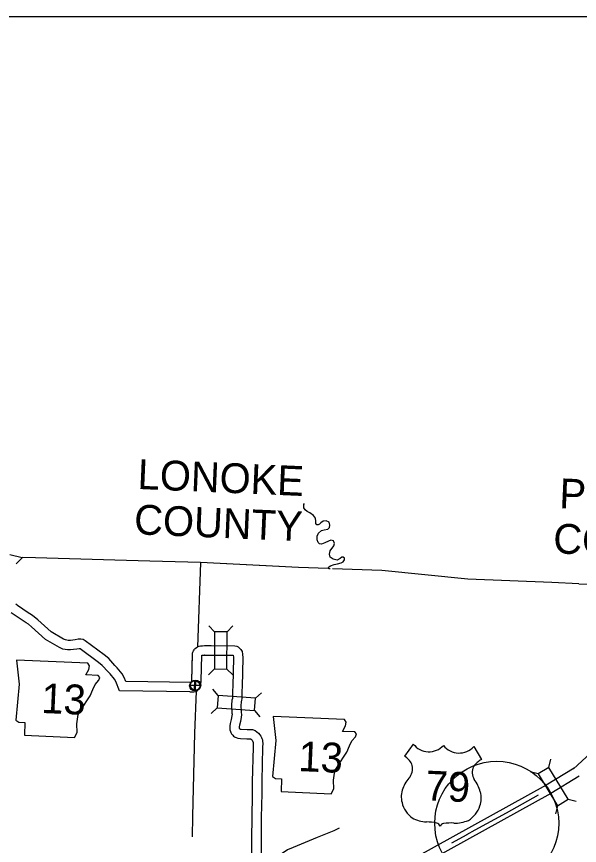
# Model space of a CAD drawing. Extents: x 1196286 to 1268366, y 2040822 to 2082115.
# Drawn here: x 1200093 to 1203681, y 2076830 to 2082115 of the extents above; entities that cross this region are included whole.
import ezdxf

# ---------------------------------------------------------------- set-up
doc = ezdxf.new("R2010")
doc.units = 0
for name, color, linetype in [('10', 7, 'Continuous'), ('55', 7, 'Continuous'), ('Default', 7, 'Continuous'), ('Level 100', 7, 'Continuous'), ('Level 78', 7, 'Continuous'), ('Level 8', 7, 'Continuous'), ('Level 84', 7, 'Continuous'), ('Level 87', 7, 'Continuous'), ('Level 95', 7, 'Continuous'), ('Level 96', 7, 'Continuous'), ('Level 98', 7, 'Continuous')]:
    doc.layers.add(name, color=color, linetype=linetype)

msp = doc.modelspace()

# ---------------------------------------------------------------- linework, layer by layer
at = {"layer": '10'}
msp.add_lwpolyline([(1202150.4, 2076940.5), (1202116.4, 2076923.6), (1202008.7, 2076880), (1201857.3, 2076817.3), (1201821, 2076800.8), (1201785.3, 2076778.5), (1201558.1, 2076623.9), (1201479.7, 2076569.9), (1201437.3, 2076546.6), (1201393.2, 2076527.1), (1201236, 2076471.6), (1201170.7, 2076445.2), (1201116.4, 2076419.2), (1201080.8, 2076396.6)], dxfattribs=at)
at = {"layer": '55'}
for points in [[(1203677.3, 2078498.2), (1204029.1, 2078492.6), (1204569.7, 2078521.8), (1204573.6, 2079234.1)], [(1202079.8, 2078594.6), (1202084.8, 2078605.7), (1202094.2, 2078612.5), (1202118.8, 2078621.3), (1202139.9, 2078625.9), (1202163.4, 2078631.3), (1202175.8, 2078638.7), (1202183, 2078651.2), (1202183.8, 2078662.4), (1202175.8, 2078667.5), (1202167.2, 2078667.2), (1202155.8, 2078660.4), (1202135.9, 2078649.3), (1202110.4, 2078654.2), (1202092.3, 2078668.5), (1202088, 2078687.5), (1202092.3, 2078707.8), (1202114.7, 2078739.6), (1202120.8, 2078754.2), (1202114.5, 2078771.3), (1202095.7, 2078776.6), (1202080.9, 2078770.7), (1202057.8, 2078759.5), (1202037, 2078751.4), (1202023.7, 2078751.9), (1202015.6, 2078760.6), (1202009, 2078778.5), (1202009.1, 2078801.9), (1202016.9, 2078820.5), (1202036.2, 2078837.8), (1202053.1, 2078842), (1202078, 2078847.3), (1202089, 2078857.6), (1202090.7, 2078872.3), (1202085.9, 2078890.5), (1202066.1, 2078898.7), (1202047.9, 2078896.9), (1202033.4, 2078887.2), (1202023.7, 2078878.3), (1202016.8, 2078874), (1202006.8, 2078874.9), (1202000.9, 2078883.5), (1202001.2, 2078896.6), (1201997.9, 2078916.3), (1201986.5, 2078933.1), (1201962.6, 2078950.4), (1201945.4, 2078959.7), (1201933.8, 2078970.1), (1201925.3, 2078983.2), (1201925.4, 2079002.9), (1201929.4, 2079009.1)], [(1200942, 2078643), (1200719.1, 2078648), (1200214.6, 2078663.6), (1200128.6, 2078666.3)], [(1201767.2, 2078607.4), (1201264.8, 2078633.9), (1200942, 2078643)], [(1202079.8, 2078594.6), (1201890, 2078601), (1201264.8, 2078633.9), (1200942, 2078643)], [(1201264.8, 2078633.9), (1201245.8, 2078094.7)], [(1201264.8, 2078633.9), (1201245.8, 2078094.7)], [(1202091.8, 2078594.2), (1202083.2, 2078594.5)], [(1203677.3, 2078498.2), (1203505.7, 2078505.7), (1202970.4, 2078527.8), (1202420.7, 2078583.1), (1202106.3, 2078593.7)], [(1201237.5, 2077813.2), (1201227.7, 2077546.2), (1201215.6, 2077015.9), (1201211.8, 2076884)], [(1201237.5, 2077812.6), (1201227.7, 2077546.2), (1201215.6, 2077015.9), (1201211.8, 2076884)]]:
    msp.add_lwpolyline(points, dxfattribs=at)
at = {"layer": 'Default'}
for p, q in [((1202621.9, 2077476.4), (1202566.6, 2077398.4)), ((1203007.6, 2077459.9), (1203056.1, 2077377.5))]:
    msp.add_line(p, q, dxfattribs=at)
msp.add_lwpolyline([(1201728.7, 2077652.5), (1201745, 2077499.4), (1201725, 2077269.1), (1201744.7, 2077255.6), (1201782.8, 2077253.9), (1201779.3, 2077172.8), (1202098.7, 2077159.1), (1202115.4, 2077191.4), (1202112.6, 2077244.9), (1202122.8, 2077305.4), (1202152.7, 2077352.4), (1202172, 2077387.1), (1202199, 2077424.1), (1202215.9, 2077464), (1202230, 2077496.4), (1202254, 2077523.3), (1202259.9, 2077540.9), (1202250.3, 2077554), (1202171.7, 2077557.3), (1202190.9, 2077592.1), (1202194.4, 2077614.8), (1202184.7, 2077632.8)], close=True, dxfattribs=at)
for centre, radius, start, end in [((1202722, 2077553.6), 126.4, 217.623, 317.2181), ((1202914.5, 2077545.3), 126.4, 217.8778, 317.4729), ((1202493.8, 2077284.9), 134.9, 28.3289, 57.5362), ((1203118.9, 2077258.1), 134.9, 117.5597, 146.767), ((1202525, 2077319.1), 92.5, 326.3584, 18.7587), ((1203090.7, 2077294.9), 92.5, 156.3372, 208.7375), ((1202758.5, 2077119.4), 215.7, 136.5044, 160.2393), ((1202841, 2077115.9), 215.7, 14.8566, 38.5915), ((1202688.1, 2077140.1), 142.6, 158.5056, 194.9298), ((1202912.9, 2077130.5), 142.6, 340.1661, 16.5903), ((1202711.3, 2077139.5), 165, 192.6554, 234.6791), ((1202889.7, 2077131.9), 165, 300.4168, 342.4405), ((1202716.6, 2077191.3), 211.8, 241.625, 267.1258), ((1202695.8, 2076591.9), 388, 78.7421, 88.5018), ((1202759.2, 2076937.4), 37.2, 25.5822, 70.5343), ((1202824.8, 2076934.6), 37.2, 104.5616, 149.5137), ((1202858.3, 2076584.9), 388, 86.5941, 96.3538), ((1202888.9, 2077183.9), 211.8, 267.9701, 293.4709)]:
    msp.add_arc(centre, radius, start, end, dxfattribs=at)
at = {"layer": 'Level 100'}
for p, q in [((1201261.7, 2077846.4), (1201196.7, 2077848.6)), ((1201202, 2077852.2), (1201267.1, 2077851)), ((1201228.1, 2077815), (1201230.3, 2077880)), ((1201233.9, 2077819.1), (1201235.2, 2077884.2))]:
    msp.add_line(p, q, dxfattribs=at)
for centre, radius in [((1201229.2, 2077847.5), 32.5), ((1201234.6, 2077851.6), 32.6)]:
    msp.add_circle(centre, radius, dxfattribs=at)
at = {"layer": 'Level 78'}
msp.add_lwpolyline([(1200092.7, 2078011.8), (1200109, 2077858.7), (1200088.9, 2077628.4), (1200108.7, 2077614.8), (1200146.7, 2077613.2), (1200143.2, 2077532.1), (1200462.7, 2077518.4), (1200479.3, 2077550.7), (1200476.5, 2077604.2), (1200486.7, 2077664.7), (1200516.7, 2077711.7), (1200536, 2077746.4), (1200562.9, 2077783.4), (1200579.9, 2077823.3), (1200594, 2077855.7), (1200618, 2077882.6), (1200623.8, 2077900.1), (1200614.2, 2077913.2), (1200535.6, 2077916.6), (1200554.9, 2077951.3), (1200558.4, 2077974), (1200548.6, 2077992)], close=True, dxfattribs=at)
at = {"layer": 'Level 8'}
msp.add_lwpolyline([(1196285.8, 2082114.9), (1207540.7, 2082114.9), (1207563, 2069523.3), (1196285.8, 2069523.3)], close=True, dxfattribs=at)
for points in [[(1202964.4, 2076899.4), (1203017.1, 2076928.9), (1203215.4, 2077038.3), (1203420.2, 2077152.8)], [(1202866.8, 2076846.1), (1202964.6, 2076899.5)]]:
    msp.add_lwpolyline(points, dxfattribs=at)
msp.add_circle((1203153.8, 2076971.3), 395.3, dxfattribs=at)
at = {"layer": 'Level 84'}
for points in [[(1204746.9, 2078438), (1204744.6, 2078433.5), (1204739.6, 2078415.9), (1204735.2, 2078403.8), (1204733, 2078396), (1204729.7, 2078385.5), (1204726.2, 2078372.7), (1204722.8, 2078362.5), (1204719, 2078350.6), (1204715.6, 2078337.7), (1204710.9, 2078325.5), (1204704.4, 2078309.6), (1204695.5, 2078294.9), (1204693.5, 2078290.6), (1204689.3, 2078285.4), (1204685.7, 2078280), (1204682.6, 2078276.6), (1204672.4, 2078266.1), (1204665.8, 2078258.9), (1203642.8, 2077318.1)], [(1203647.6, 2077321.7), (1203469.2, 2077213.2), (1202397.6, 2076620.1), (1202358.9, 2076604.5), (1202331.8, 2076591.8), (1202297.8, 2076576.5), (1202278, 2076569.9), (1202246.6, 2076561.7), (1202206.6, 2076555.5), (1201875.5, 2076511.7), (1201613.8, 2076477.3), (1201433.8, 2076454.5), (1201422.2, 2076453.1), (1201405.9, 2076452.7), (1201391.5, 2076453), (1201353.5, 2076452.1), (1201200.1, 2076454.6)], [(1203678.7, 2077270.4), (1203499.3, 2077161.3), (1202423.5, 2076565.9), (1202382.9, 2076549.5), (1202356.9, 2076537.2), (1202319.6, 2076520.6), (1202295.1, 2076512.4), (1202258.8, 2076502.9), (1202215.1, 2076496.1), (1201883.3, 2076452.2), (1201621.5, 2076417.8), (1201441.1, 2076395), (1201426.6, 2076393.2), (1201406.2, 2076392.6), (1201391.5, 2076393), (1201353.7, 2076392.1), (1201197.9, 2076394.6), (1201197.6, 2076394.6)]]:
    msp.add_lwpolyline(points, dxfattribs=at)
at = {"layer": 'Level 87'}
for p, q in [((1201278.5, 2078103.4), (1201292, 2078103.8)), ((1201214.2, 2078047.5), (1201214.5, 2078050.6)), ((1201293.5, 2078043.8), (1201291.8, 2078043.8)), ((1201209.8, 2077882.5), (1201209.6, 2077879.9)), ((1201269.4, 2077875.7), (1201269.6, 2077878.3)), ((1201212.8, 2077808.5), (1201216.5, 2077808.6))]:
    msp.add_line(p, q, dxfattribs=at)
for points in [[(1201209.6, 2077879.9), (1201214.4, 2078053.3)], [(1201214.4, 2078053.3), (1201217.1, 2078062.3), (1201220.1, 2078069.6), (1201224.6, 2078076.3), (1201228.1, 2078080.4), (1201232.6, 2078085.3), (1201239.7, 2078091), (1201247.6, 2078095.8), (1201256.6, 2078099.4), (1201265.1, 2078101.8), (1201273.5, 2078102.8), (1201291.1, 2078103.8)], [(1201214.5, 2078050.6), (1201215.2, 2078055.9), (1201217.1, 2078062.3), (1201220.1, 2078069.6), (1201224.6, 2078076.3), (1201228.1, 2078080.4), (1201232.6, 2078085.3), (1201239.7, 2078091), (1201247.6, 2078095.8), (1201256.6, 2078099.4), (1201265.1, 2078101.8), (1201278.5, 2078103.4)], [(1201291.1, 2078103.8), (1201485.6, 2078103.2)], [(1201292, 2078103.8), (1201334.1, 2078103.6)], [(1201485.6, 2078103.2), (1201497.1, 2078099.4), (1201504.8, 2078095.2), (1201514.6, 2078088.2), (1201523.2, 2078079.2), (1201531.4, 2078066.1), (1201534.3, 2078049.1), (1201536.3, 2078025.4)], [(1201209.6, 2077879.9), (1201214.2, 2078047.5)], [(1201269.6, 2077878.3), (1201274.1, 2078042.8)], [(1201269.6, 2077878.3), (1201274.1, 2078042.8)], [(1201274.1, 2078042.8), (1201292.7, 2078043.8)], [(1201274.1, 2078042.8), (1201293.5, 2078043.8)], [(1201291.8, 2078043.8), (1201474.6, 2078043.2)], [(1201292.7, 2078043.8), (1201333.9, 2078043.6)], [(1201476.3, 2078025.3), (1201470.8, 2077845.3)], [(1201474.6, 2078043.2), (1201475.8, 2078029.2), (1201476.4, 2078022.1)], [(1201536.3, 2078025.4), (1201530.8, 2077844)], [(1201208.2, 2077869.1), (1200790.4, 2077874.8)], [(1201200.2, 2077869.2), (1201208.2, 2077868.8)], [(1201208.2, 2077869.1), (1201209.8, 2077882.5)], [(1201208.2, 2077868.8), (1201209.8, 2077882.5)], [(1201212.8, 2077808.5), (1201224.2, 2077809.2), (1201235.6, 2077812.1), (1201246.2, 2077818), (1201255.8, 2077826.3), (1201262.5, 2077837.8), (1201265.6, 2077848.1), (1201267.7, 2077861.1), (1201269.6, 2077878.3)], [(1201216.5, 2077808.6), (1201224.2, 2077809.2), (1201235.6, 2077812.1), (1201246.2, 2077818), (1201255.8, 2077826.3), (1201262.5, 2077837.8), (1201265.6, 2077848.1), (1201267.7, 2077861.1), (1201269.4, 2077875.7)], [(1201470.8, 2077845.3), (1201470.2, 2077815.5), (1201469.7, 2077779.6), (1201469.3, 2077770.4), (1201468.8, 2077767.2), (1201466.4, 2077756.1), (1201465.1, 2077744.9), (1201463.9, 2077735), (1201462.6, 2077724.4), (1201462.6, 2077706), (1201464.9, 2077689), (1201466.2, 2077674.2), (1201466.7, 2077666.4), (1201465.1, 2077656.4), (1201461, 2077632.4), (1201455.7, 2077608.2), (1201453.2, 2077592.9), (1201452.4, 2077581.4), (1201453.7, 2077567.3), (1201456.1, 2077556.7), (1201459, 2077549.2), (1201462.9, 2077541.9), (1201467.1, 2077536.7), (1201471.1, 2077531.9), (1201476.9, 2077526.7), (1201482.2, 2077523.1), (1201487.7, 2077519.8), (1201493.2, 2077517.2), (1201503.5, 2077513.2), (1201520.6, 2077511), (1201561, 2077509.6), (1201585.9, 2077509.3), (1201587.1, 2077508.4), (1201591.8, 2077504.4), (1201594.8, 2077500.4), (1201598.2, 2077495.3), (1201600.3, 2077491.4), (1201601.1, 2077489.8), (1201601.8, 2077487.5), (1201602.1, 2077485.9), (1201602.3, 2077481.8), (1201601.4, 2077457.2), (1201596.1, 2077234.3), (1201595.6, 2077154.5)], [(1201530.8, 2077844), (1201530.2, 2077814.4), (1201529.7, 2077778), (1201529.1, 2077764.7), (1201527.8, 2077756.2), (1201525.6, 2077746.2), (1201524.7, 2077737.9), (1201523.4, 2077727.7), (1201522.6, 2077720.8), (1201522.6, 2077710.1), (1201524.5, 2077695.6), (1201526, 2077678.8), (1201527, 2077663.6), (1201524.3, 2077646.6), (1201519.9, 2077620.9), (1201514.7, 2077597), (1201512.9, 2077586), (1201512.6, 2077582), (1201513.1, 2077576.7), (1201513.6, 2077574.7), (1201514.3, 2077573.8), (1201514.3, 2077573.8), (1201514.7, 2077573.5), (1201515.7, 2077572.9), (1201517, 2077572.3), (1201518.4, 2077571.8), (1201525.4, 2077570.9), (1201562.4, 2077569.6), (1201596.7, 2077569.2), (1201613.9, 2077563.5), (1201625.1, 2077554.9), (1201635.8, 2077545.6), (1201643.7, 2077535.2), (1201649.6, 2077526.4), (1201653.7, 2077518.8), (1201657.3, 2077511.5), (1201660, 2077502.2), (1201661.9, 2077493.1), (1201662.3, 2077481.7), (1201661.3, 2077455.2), (1201656.6, 2077241.7), (1201655.7, 2077160.2)], [(1201198.4, 2077809.2), (1200750.4, 2077815.4)], [(1201197.5, 2077809.2), (1201212.8, 2077808.5)], [(1201197.5, 2077809.2), (1201212.8, 2077808.5)], [(1201595.6, 2077154.5), (1201593, 2077008.4), (1201591.5, 2076874.7), (1201587.9, 2076474)], [(1201655.7, 2077160.2), (1201653, 2077007.6), (1201651.5, 2076874.1), (1201647.9, 2076481.8)]]:
    msp.add_lwpolyline(points, dxfattribs=at)
at = {"layer": 'Level 95'}
for points in [[(1200090.4, 2078625.4), (1200128.6, 2078664.6), (1200049.9, 2078683.2)], [(1200790.4, 2077874.8), (1200779.2, 2077901.4), (1200766.6, 2077923.2), (1200735.1, 2077962.9), (1200720.7, 2077977.9), (1200680.4, 2078021.1), (1200652.1, 2078044.3), (1200531.4, 2078134.2), (1200518.7, 2078142), (1200503.2, 2078144.1), (1200486.6, 2078144.5), (1200467.2, 2078140.2), (1200451.4, 2078137.9), (1200436.5, 2078137.1), (1200422.7, 2078137.5), (1200405.2, 2078140), (1200393.4, 2078145.3), (1200313.5, 2078190.8), (1200228.6, 2078268), (1200205.1, 2078288), (1200188.5, 2078299.2), (1200168.3, 2078312.5), (1200098.3, 2078360.1), (1200089.6, 2078369.1)], [(1200750.4, 2077815.4), (1200725.3, 2077874.7), (1200716.9, 2077889.4), (1200689.9, 2077923.3), (1200677.1, 2077936.6), (1200639.3, 2077977.2), (1200615.1, 2077997), (1200498.1, 2078084.2), (1200492.5, 2078084.3), (1200477.9, 2078081.1), (1200457.2, 2078078.2), (1200437.4, 2078077.1), (1200417.7, 2078077.6), (1200388.3, 2078081.8), (1200366.2, 2078091.8), (1200278.1, 2078141.9), (1200189, 2078222.9), (1200168.8, 2078240.1), (1200155.2, 2078249.2), (1200134.9, 2078262.6), (1200059.4, 2078314)]]:
    msp.add_lwpolyline(points, dxfattribs=at)
at = {"layer": 'Level 98'}
for p, q in [((1201355.6, 2078192.4), (1201318.3, 2078229.8)), ((1201434.8, 2078192.1), (1201472.2, 2078229.3)), ((1201354.8, 2077954.8), (1201317.3, 2077917.6)), ((1201434, 2077954.5), (1201471.2, 2077917.1)), ((1201378.3, 2077785.6), (1201343.7, 2077825.5)), ((1201615.3, 2077769), (1201655.2, 2077803.6)), ((1201372.8, 2077706.6), (1201332.9, 2077672)), ((1201609.8, 2077690), (1201644.4, 2077650.1)), ((1203486.1, 2077327.5), (1203498.6, 2077378.8)), ((1203418.4, 2077286.3), (1203367.1, 2077298.8)), ((1203609.5, 2077124.4), (1203660.8, 2077111.9)), ((1203541.9, 2077083.3), (1203529.4, 2077032))]:
    msp.add_line(p, q, dxfattribs=at)
for points in [[(1201355.6, 2078192.4), (1201354.8, 2077954.8), (1201434, 2077954.5), (1201434.8, 2078192.1)], [(1201372.8, 2077706.6), (1201609.8, 2077690), (1201615.3, 2077769), (1201378.3, 2077785.6)], [(1203609.5, 2077124.4), (1203486.1, 2077327.5), (1203418.4, 2077286.3), (1203541.9, 2077083.3)]]:
    msp.add_lwpolyline(points, close=True, dxfattribs=at)

# ---------------------------------------------------------------- texts
at = {"layer": 'Default'}
for s, p in [('13', (1201887.2, 2077304.2)), ('79', (1202697.4, 2077117.3))]:
    msp.add_text(s, height=190.08, rotation=357.548, dxfattribs=at).set_placement(p)
at = {"layer": 'Level 78'}
msp.add_text('13', height=190.08, rotation=357.548, dxfattribs=at).set_placement((1200248.3, 2077674.7))
at = {"layer": 'Level 96'}
for s, p in [('LONOKE', (1200862.2, 2079103)), ('PRAIRIE', (1203550.2, 2078980.8)), ('COUNTY', (1200839.8, 2078814.7)), ('COUNTY', (1203511.3, 2078693.2))]:
    msp.add_text(s, height=190.08, rotation=357.548, dxfattribs=at).set_placement(p)

doc.saveas('drawing.dxf')
